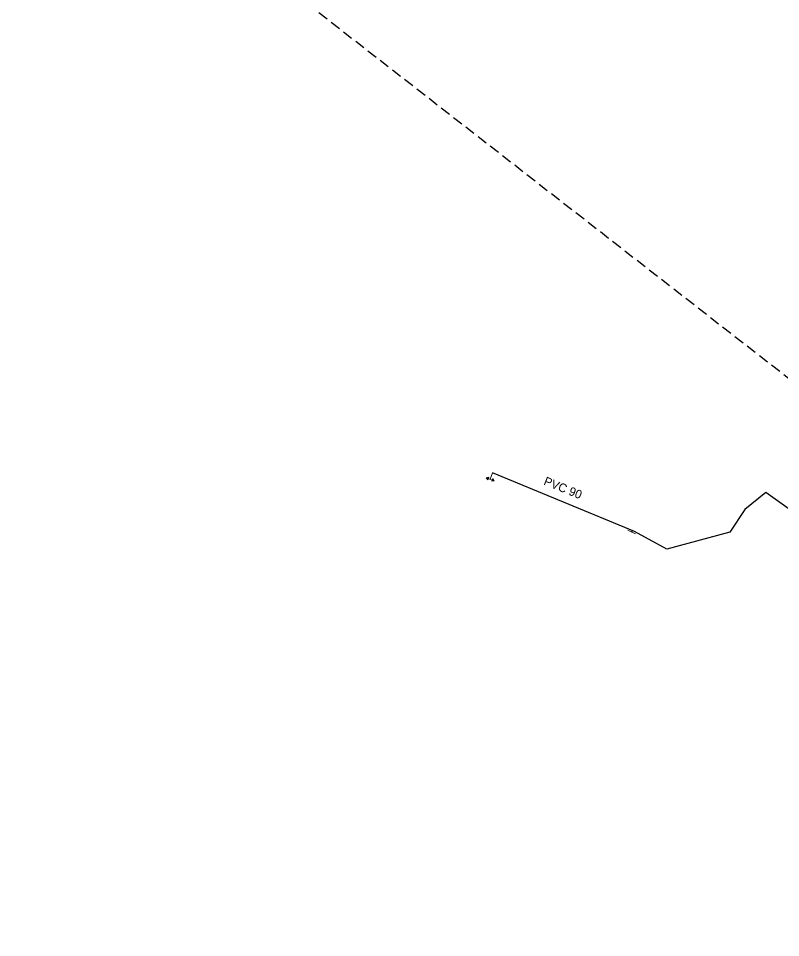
# Model space of a CAD drawing. Extents: x -683466 to -682479, y -996772 to -995963.
# Drawn here: x -682861 to -682772.5, y -996467.6 to -996360.9 of the extents above; entities that cross this region are included whole.
import ezdxf

# ---------------------------------------------------------------- set-up
doc = ezdxf.new("R2010")
doc.units = 0
doc.header["$LTSCALE"] = 0.4
doc.linetypes.add('MEDIUM_DASHED', pattern=[4.5, 3, -1.5])
doc.layers.add('1', color=7, linetype='Continuous')
for name, color, linetype, lineweight in [('14', 7, 'Continuous', 25), ('17', 7, 'Continuous', 25), ('34', 7, 'Continuous', 13), ('63', 7, 'MEDIUM_DASHED', 25)]:
    doc.layers.add(name, color=color, linetype=linetype, lineweight=lineweight)

msp = doc.modelspace()

# ---------------------------------------------------------------- linework, layer by layer
at = {"layer": '14', "lineweight": 13}
msp.add_line((-682789.678, -996420.322), (-682789.76, -996420.5), dxfattribs=at)
at = {"layer": '17'}
msp.add_lwpolyline([(-682751.718, -996421.207), (-682760.52, -996423.84), (-682765.68, -996421.989), (-682774.19, -996415.899), (-682776.629, -996417.879), (-682778.359, -996420.489), (-682785.68, -996422.469), (-682789.414, -996420.431), (-682805.899, -996413.609)], dxfattribs=at)
at = {"layer": '34'}
for p, q in [((-682806.63, -996414.205), (-682806.618, -996414.175)), ((-682806.608, -996414.229), (-682806.587, -996414.17)), ((-682806.592, -996414.255), (-682806.557, -996414.16)), ((-682806.576, -996414.279), (-682806.53, -996414.153)), ((-682806.555, -996414.302), (-682806.499, -996414.147)), ((-682806.54, -996414.326), (-682806.472, -996414.141)), ((-682806.522, -996414.348), (-682806.444, -996414.134)), ((-682806.506, -996414.376), (-682806.414, -996414.124)), ((-682806.486, -996414.399), (-682806.383, -996414.119)), ((-682806.182, -996414.357), (-682805.899, -996413.609)), ((-682805.981, -996414.59), (-682805.873, -996414.312)), ((-682805.951, -996414.586), (-682805.853, -996414.336)), ((-682805.921, -996414.576), (-682805.838, -996414.363)), ((-682805.892, -996414.57), (-682805.821, -996414.387)), ((-682805.888, -996414.289), (-682805.718, -996414.533)), ((-682805.865, -996414.564), (-682805.805, -996414.409)), ((-682805.834, -996414.559), (-682805.785, -996414.434)), ((-682805.806, -996414.553), (-682805.769, -996414.458)), ((-682805.777, -996414.543), (-682805.754, -996414.485)), ((-682805.745, -996414.54), (-682805.734, -996414.51)), ((-682789.305, -996420.708), (-682790.214, -996420.29))]:
    msp.add_line(p, q, dxfattribs=at)
for points in [[(-682806.646, -996414.182), (-682806.469, -996414.423), (-682806.356, -996414.112)], [(-682806.356, -996414.112), (-682806.646, -996414.182), (-682805.718, -996414.533)], [(-682805.718, -996414.533), (-682806.009, -996414.597), (-682805.888, -996414.289)]]:
    msp.add_lwpolyline(points, dxfattribs=at)
at = {"layer": '63'}
msp.add_lwpolyline([(-683425.281, -996021.839), (-683425.281, -996016.256), (-683425.281, -996016.256), (-683335.962, -995963.223), (-683335.962, -995963.223), (-682479.059, -996630.324), (-682479.059, -996630.324), (-682551.631, -996711.269), (-682551.631, -996711.269), (-683416.907, -996083.246), (-683416.907, -996083.246)], close=True, dxfattribs=at)

# ---------------------------------------------------------------- texts
at = {"layer": '1'}
msp.add_text('PVC 90', height=1, rotation=338, dxfattribs=at).set_placement((-682800.052, -996414.962))

doc.saveas('drawing.dxf')
